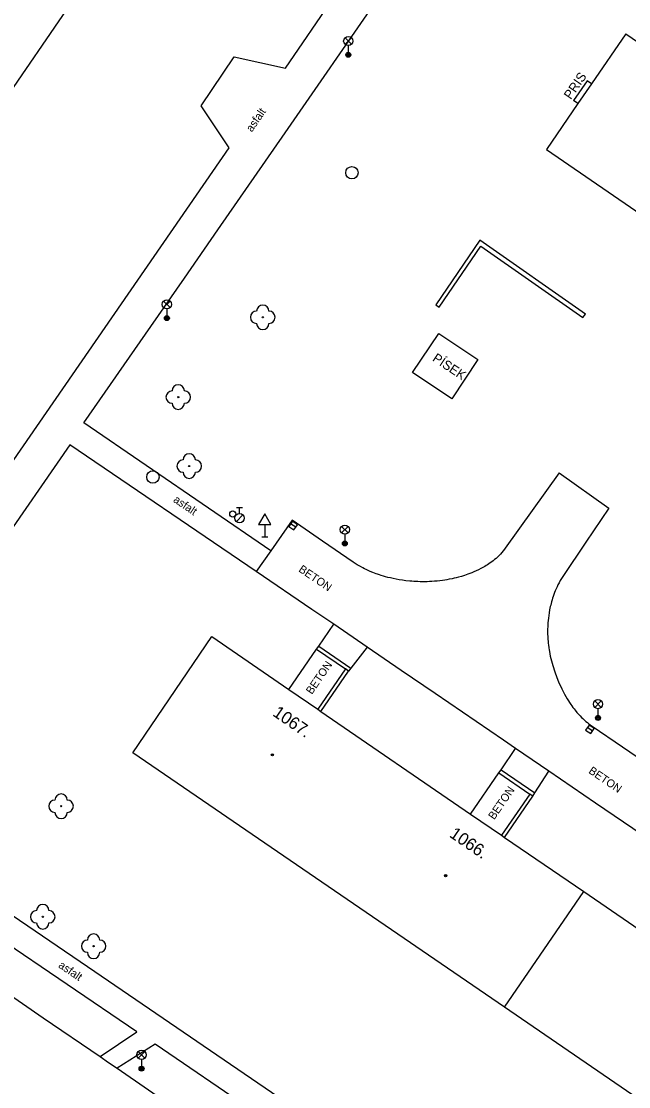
# Model space of a CAD drawing. Extents: x -539515 to -538098, y -1182060 to -1180157.
# Drawn here: x -538801 to -538751.7, y -1181426.9 to -1181340.3 of the extents above; entities that cross this region are included whole.
import ezdxf

# ---------------------------------------------------------------- set-up
doc = ezdxf.new("R2010")
doc.units = 0
for name, color, linetype in [('Vrstva 10', 7, 'Continuous'), ('Vrstva 11', 7, 'Continuous'), ('Vrstva 22', 7, 'Continuous'), ('Vrstva 24', 7, 'Continuous'), ('Vrstva 27', 7, 'Continuous'), ('Vrstva 28', 7, 'Continuous'), ('Vrstva 33', 7, 'Continuous'), ('Vrstva 34', 7, 'Continuous'), ('Vrstva 39', 7, 'Continuous'), ('Vrstva 40', 7, 'Continuous'), ('Vrstva 41', 7, 'Continuous'), ('Vrstva 47', 7, 'Continuous'), ('Vrstva 5', 7, 'Continuous'), ('Vrstva 7', 7, 'Continuous')]:
    doc.layers.add(name, color=color, linetype=linetype)

msp = doc.modelspace()

# ---------------------------------------------------------------- linework, layer by layer
at = {"layer": 'Vrstva 10'}
for p, q in [((-538769.24, -1181368.85), (-538767.12, -1181365.67)), ((-538767.12, -1181365.67), (-538763.94, -1181367.79)), ((-538763.94, -1181367.79), (-538766.06, -1181370.97)), ((-538766.06, -1181370.97), (-538769.24, -1181368.85)), ((-538757.34, -1181376.98), (-538753.31, -1181379.85)), ((-538777.44, -1181388.08), (-538781.95, -1181385.01)), ((-538761.875, -1181398.709), (-538767.4, -1181394.926)), ((-538754.816, -1181397.466), (-538754.67, -1181397.57)), ((-538754.67, -1181397.57), (-538744.795, -1181404.321)), ((-538803.861, -1181418.09), (-538799.239, -1181421.248)), ((-538799.239, -1181421.248), (-538794.62, -1181424.41))]:
    msp.add_line(p, q, dxfattribs=at)
for points in [[(-538757.34, -1181376.98), (-538759.53, -1181380.05), (-538761.72, -1181383.12), (-538761.775, -1181383.195), (-538761.887, -1181383.339), (-538762.002, -1181383.474), (-538762.118, -1181383.602), (-538762.236, -1181383.721), (-538762.353, -1181383.833), (-538762.471, -1181383.939), (-538762.589, -1181384.038), (-538762.706, -1181384.131), (-538762.822, -1181384.219), (-538762.937, -1181384.302), (-538763.05, -1181384.38), (-538763.162, -1181384.453), (-538763.271, -1181384.522), (-538763.379, -1181384.587), (-538763.485, -1181384.648)], [(-538753.31, -1181379.85), (-538755.175, -1181382.625), (-538757.04, -1181385.4), (-538757.152, -1181385.572), (-538757.254, -1181385.744), (-538757.349, -1181385.913), (-538757.437, -1181386.081), (-538757.517, -1181386.246), (-538757.591, -1181386.409), (-538757.659, -1181386.568), (-538757.721, -1181386.725), (-538757.778, -1181386.879), (-538757.83, -1181387.029), (-538757.878, -1181387.176), (-538757.922, -1181387.32), (-538757.962, -1181387.46), (-538757.998, -1181387.597), (-538758.031, -1181387.73), (-538758.062, -1181387.86), (-538758.114, -1181388.113), (-538758.157, -1181388.351)], [(-538779.02, -1181380.84), (-538780.762, -1181383.32), (-538781.95, -1181385.01)], [(-538773.282, -1181384.718), (-538773.488, -1181384.607), (-538773.64, -1181384.52), (-538773.752, -1181384.453), (-538773.918, -1181384.349), (-538774.08, -1181384.24), (-538776.55, -1181382.54), (-538779.02, -1181380.84)], [(-538763.485, -1181384.648), (-538763.694, -1181384.762), (-538763.894, -1181384.863), (-538764.084, -1181384.952), (-538764.264, -1181385.032), (-538764.435, -1181385.104), (-538764.597, -1181385.167), (-538764.749, -1181385.224), (-538764.893, -1181385.274), (-538765.028, -1181385.32), (-538765.282, -1181385.399), (-538765.506, -1181385.463), (-538765.701, -1181385.514), (-538765.871, -1181385.555), (-538766.02, -1181385.589), (-538766.28, -1181385.642), (-538766.472, -1181385.678), (-538766.616, -1181385.702), (-538766.829, -1181385.733), (-538767.04, -1181385.76), (-538767.255, -1181385.783), (-538767.467, -1181385.801), (-538767.673, -1181385.815), (-538767.876, -1181385.825), (-538768.073, -1181385.832), (-538768.266, -1181385.835), (-538768.453, -1181385.835), (-538768.636, -1181385.832), (-538768.814, -1181385.826), (-538768.987, -1181385.819), (-538769.155, -1181385.809), (-538769.318, -1181385.797), (-538769.476, -1181385.783), (-538769.783, -1181385.751), (-538770.07, -1181385.713), (-538770.34, -1181385.671), (-538770.591, -1181385.626), (-538770.827, -1181385.579), (-538771.046, -1181385.53), (-538771.251, -1181385.48), (-538771.442, -1181385.43), (-538771.619, -1181385.379), (-538771.785, -1181385.329), (-538771.939, -1181385.28), (-538772.083, -1181385.231), (-538772.217, -1181385.184), (-538772.465, -1181385.09), (-538772.679, -1181385.002), (-538772.864, -1181384.921), (-538773.024, -1181384.847), (-538773.162, -1181384.779), (-538773.282, -1181384.718)], [(-538772.93, -1181391.15), (-538775.653, -1181389.296), (-538777.44, -1181388.08)], [(-538758.157, -1181388.351), (-538758.191, -1181388.576), (-538758.218, -1181388.788), (-538758.239, -1181388.986), (-538758.255, -1181389.173), (-538758.267, -1181389.347), (-538758.275, -1181389.511), (-538758.279, -1181389.665), (-538758.282, -1181389.808), (-538758.28, -1181390.076), (-538758.272, -1181390.309), (-538758.261, -1181390.512), (-538758.247, -1181390.689), (-538758.233, -1181390.842), (-538758.218, -1181390.975), (-538758.187, -1181391.206), (-538758.16, -1181391.378), (-538758.138, -1181391.505), (-538758.101, -1181391.694), (-538758.06, -1181391.88), (-538758.013, -1181392.076), (-538757.964, -1181392.267), (-538757.913, -1181392.453), (-538757.861, -1181392.634), (-538757.808, -1181392.81), (-538757.753, -1181392.981), (-538757.698, -1181393.147), (-538757.642, -1181393.307), (-538757.586, -1181393.463), (-538757.529, -1181393.613), (-538757.472, -1181393.758), (-538757.356, -1181394.038), (-538757.24, -1181394.299), (-538757.126, -1181394.541), (-538757.013, -1181394.765), (-538756.903, -1181394.973), (-538756.795, -1181395.166), (-538756.69, -1181395.343), (-538756.589, -1181395.508), (-538756.49, -1181395.66), (-538756.396, -1181395.8), (-538756.305, -1181395.929), (-538756.218, -1181396.049), (-538756.134, -1181396.159), (-538756.054, -1181396.261), (-538755.9, -1181396.448), (-538755.761, -1181396.606), (-538755.636, -1181396.741), (-538755.524, -1181396.856), (-538755.424, -1181396.954), (-538755.335, -1181397.038), (-538755.175, -1181397.181), (-538755.053, -1181397.283), (-538754.959, -1181397.358), (-538754.816, -1181397.466)], [(-538767.4, -1181394.926), (-538770.164, -1181393.036), (-538772.93, -1181391.15)], [(-538758.19, -1181401.23), (-538760.881, -1181399.388), (-538761.875, -1181398.709)], [(-538750.603, -1181406.405), (-538754.398, -1181403.819), (-538758.19, -1181401.23)], [(-538794.62, -1181424.41), (-538793.935, -1181424.88), (-538793.25, -1181425.35), (-538790.692, -1181427.114), (-538786.861, -1181429.767)]]:
    msp.add_lwpolyline(points, dxfattribs=at)
at = {"layer": 'Vrstva 11'}
for p, q in [((-538779.58, -1181344.11), (-538765.75, -1181323.99)), ((-538779.601, -1181349.363), (-538771.42, -1181337.527)), ((-538786.42, -1181347.18), (-538783.75, -1181343.19)), ((-538783.75, -1181343.19), (-538779.58, -1181344.11)), ((-538784.14, -1181350.6), (-538786.42, -1181347.18)), ((-538785.06, -1181357.25), (-538779.601, -1181349.363)), ((-538819.07, -1181401.16), (-538784.14, -1181350.6)), ((-538795.95, -1181372.94), (-538790.503, -1181365.096)), ((-538780.762, -1181383.32), (-538795.95, -1181372.94)), ((-538797.09, -1181374.73), (-538816.55, -1181402.85)), ((-538781.95, -1181385.01), (-538797.09, -1181374.73)), ((-538777.038, -1181391.315), (-538774.697, -1181392.92)), ((-538776.868, -1181391.067), (-538774.264, -1181392.852)), ((-538762.061, -1181401.108), (-538759.309, -1181402.995)), ((-538762.231, -1181401.356), (-538759.717, -1181403.08)), ((-538816.55, -1181402.85), (-538795.05, -1181417.505)), ((-538791.63, -1181422.39), (-538817.84, -1181404.65)), ((-538795.05, -1181417.505), (-538773.55, -1181432.16)), ((-538794.62, -1181424.41), (-538791.63, -1181422.39)), ((-538790.14, -1181423.41), (-538793.25, -1181425.35)), ((-538761.68, -1181442.8), (-538790.14, -1181423.41))]:
    msp.add_line(p, q, dxfattribs=at)
for points in [[(-538790.503, -1181365.096), (-538787.78, -1181361.174), (-538785.06, -1181357.25)], [(-538779.286, -1181394.593), (-538777.038, -1181391.315), (-538776.868, -1181391.067), (-538775.653, -1181389.296)], [(-538772.93, -1181391.15), (-538774.264, -1181392.852), (-538774.45, -1181393.09)], [(-538764.533, -1181404.712), (-538762.231, -1181401.356), (-538762.061, -1181401.108), (-538760.881, -1181399.388)], [(-538759.47, -1181403.25), (-538759.309, -1181402.995), (-538758.19, -1181401.23)]]:
    msp.add_lwpolyline(points, dxfattribs=at)
at = {"layer": 'Vrstva 22'}
for centre in [(-538781.41, -1181364.36), (-538788.28, -1181370.84), (-538787.39, -1181376.44), (-538797.79, -1181404.07), (-538799.28, -1181413.05), (-538795.15, -1181415.44)]:
    msp.add_circle(centre, 0.05, dxfattribs=at)
for centre, start, end in [((-538781.91, -1181364.36), 90, 270), ((-538781.41, -1181363.86), 0, 180), ((-538780.91, -1181364.36), 270, 90), ((-538781.41, -1181364.86), 180, 0), ((-538788.28, -1181370.34), 0, 180), ((-538788.78, -1181370.84), 90, 270), ((-538787.78, -1181370.84), 270, 90), ((-538788.28, -1181371.34), 180, 0), ((-538787.89, -1181376.44), 90, 270), ((-538787.39, -1181375.94), 0, 180), ((-538786.89, -1181376.44), 270, 90), ((-538787.39, -1181376.94), 180, 0), ((-538798.29, -1181404.07), 90, 270), ((-538797.79, -1181403.57), 0, 180), ((-538797.29, -1181404.07), 270, 90), ((-538797.79, -1181404.57), 180, 0), ((-538799.28, -1181412.55), 0, 180), ((-538799.78, -1181413.05), 90, 270), ((-538798.78, -1181413.05), 270, 90), ((-538799.28, -1181413.55), 180, 0), ((-538795.65, -1181415.44), 90, 270), ((-538795.15, -1181414.94), 0, 180), ((-538794.65, -1181415.44), 270, 90), ((-538795.15, -1181415.94), 180, 0)]:
    msp.add_arc(centre, 0.5, start, end, dxfattribs=at)
at = {"layer": 'Vrstva 24'}
for p, q in [((-538755.075, -1181345.137), (-538756.18, -1181346.75)), ((-538754.719, -1181345.381), (-538755.075, -1181345.137)), ((-538755.823, -1181346.994), (-538756.18, -1181346.75))]:
    msp.add_line(p, q, dxfattribs=at)
at = {"layer": 'Vrstva 27'}
for p, q in [((-538778.738, -1181381.416), (-538779.15, -1181381.134)), ((-538754.636, -1181397.964), (-538755.048, -1181397.682))]:
    msp.add_line(p, q, dxfattribs=at)
for points in [[(-538778.596, -1181381.21), (-538779.009, -1181380.927), (-538779.292, -1181381.34), (-538778.879, -1181381.623)], [(-538754.494, -1181397.758), (-538754.907, -1181397.475), (-538755.19, -1181397.888), (-538754.777, -1181398.171)]]:
    msp.add_lwpolyline(points, close=True, dxfattribs=at)
for centre in [(-538774.17, -1181352.61), (-538790.34, -1181377.33)]:
    msp.add_circle(centre, 0.5, dxfattribs=at)
at = {"layer": 'Vrstva 28'}
for p, q in [((-538783.558, -1181380.942), (-538783.028, -1181380.412)), ((-538783.55, -1181379.795), (-538783.05, -1181379.795)), ((-538783.3, -1181380.295), (-538783.3, -1181379.795))]:
    msp.add_line(p, q, dxfattribs=at)
for centre, radius in [((-538783.85, -1181380.34), 0.25), ((-538783.3, -1181380.67), 0.375)]:
    msp.add_circle(centre, radius, dxfattribs=at)
at = {"layer": 'Vrstva 33'}
for p, q in [((-538774.735, -1181342.18), (-538774.205, -1181341.65)), ((-538774.735, -1181341.65), (-538774.205, -1181342.18)), ((-538774.47, -1181342.29), (-538774.47, -1181343.04)), ((-538789.465, -1181363.57), (-538788.935, -1181363.04)), ((-538789.465, -1181363.04), (-538788.935, -1181363.57)), ((-538789.2, -1181363.68), (-538789.2, -1181364.43)), ((-538775.015, -1181381.87), (-538774.485, -1181381.34)), ((-538775.015, -1181381.34), (-538774.485, -1181381.87)), ((-538774.75, -1181381.98), (-538774.75, -1181382.73)), ((-538754.455, -1181396.04), (-538753.925, -1181395.51)), ((-538754.455, -1181395.51), (-538753.925, -1181396.04)), ((-538754.19, -1181396.15), (-538754.19, -1181396.9)), ((-538791.525, -1181424.53), (-538790.995, -1181424)), ((-538791.525, -1181424), (-538790.995, -1181424.53)), ((-538791.26, -1181424.64), (-538791.26, -1181425.39))]:
    msp.add_line(p, q, dxfattribs=at)
for centre, radius in [((-538774.47, -1181341.915), 0.375), ((-538774.47, -1181343.04), 0.2), ((-538774.47, -1181343.04), 0.145), ((-538774.47, -1181343.04), 0.0876), ((-538789.2, -1181363.305), 0.375), ((-538789.2, -1181364.43), 0.2), ((-538789.2, -1181364.43), 0.145), ((-538789.2, -1181364.43), 0.0876), ((-538774.75, -1181381.605), 0.375), ((-538774.75, -1181382.73), 0.2), ((-538774.75, -1181382.73), 0.145), ((-538774.75, -1181382.73), 0.0876), ((-538754.19, -1181395.775), 0.375), ((-538754.19, -1181396.9), 0.2), ((-538754.19, -1181396.9), 0.145), ((-538754.19, -1181396.9), 0.0876), ((-538791.26, -1181424.265), 0.375), ((-538791.26, -1181425.39), 0.2), ((-538791.26, -1181425.39), 0.145), ((-538791.26, -1181425.39), 0.0876)]:
    msp.add_circle(centre, radius, dxfattribs=at)
at = {"layer": 'Vrstva 34'}
for p, q in [((-538781.251, -1181381.18), (-538781.251, -1181382.198)), ((-538781.501, -1181382.198), (-538781.001, -1181382.198))]:
    msp.add_line(p, q, dxfattribs=at)
msp.add_lwpolyline([(-538781.751, -1181381.18), (-538780.751, -1181381.18), (-538781.251, -1181380.314)], close=True, dxfattribs=at)
at = {"layer": 'Vrstva 39'}
for centre, radius in [((-538780.635, -1181399.896), 0.09), ((-538780.635, -1181399.896), 0.0398), ((-538766.568, -1181409.705), 0.09), ((-538766.568, -1181409.705), 0.0398)]:
    msp.add_circle(centre, radius, dxfattribs=at)
at = {"layer": 'Vrstva 5'}
for p, q in [((-538829.45, -1181386.2), (-538788.38, -1181326.32)), ((-538758.38, -1181350.73), (-538683.63, -1181402.09)), ((-538791.96, -1181399.73), (-538785.56, -1181390.29)), ((-538761.787, -1181420.406), (-538755.349, -1181411.011))]:
    msp.add_line(p, q, dxfattribs=at)
for points in [[(-538751.94, -1181341.32), (-538754.719, -1181345.381), (-538755.823, -1181346.994), (-538758.38, -1181350.73)], [(-538751.94, -1181341.32), (-538745.831, -1181345.515)], [(-538785.56, -1181390.29), (-538779.286, -1181394.593)], [(-538779.286, -1181394.593), (-538776.945, -1181396.198)], [(-538776.945, -1181396.198), (-538776.698, -1181396.368)], [(-538776.698, -1181396.368), (-538764.533, -1181404.712)], [(-538761.787, -1181420.406), (-538791.96, -1181399.73)], [(-538764.533, -1181404.712), (-538762.019, -1181406.436)], [(-538762.019, -1181406.436), (-538761.772, -1181406.606)], [(-538761.772, -1181406.606), (-538755.349, -1181411.011)], [(-538755.349, -1181411.011), (-538749.475, -1181415.04)], [(-538731.98, -1181440.83), (-538761.787, -1181420.406)]]:
    msp.add_lwpolyline(points, dxfattribs=at)
at = {"layer": 'Vrstva 7'}
for p, q in [((-538767.081, -1181363.537), (-538763.7, -1181358.58)), ((-538763.7, -1181358.58), (-538755.411, -1181364.377)), ((-538774.697, -1181392.92), (-538776.945, -1181396.198)), ((-538759.717, -1181403.08), (-538762.019, -1181406.436))]:
    msp.add_line(p, q, dxfattribs=at)
for points in [[(-538763.79, -1181358.09), (-538767.37, -1181363.34), (-538767.081, -1181363.537)], [(-538755.411, -1181364.377), (-538755.21, -1181364.09), (-538763.79, -1181358.09)], [(-538776.698, -1181396.368), (-538774.45, -1181393.09), (-538774.697, -1181392.92)], [(-538761.772, -1181406.606), (-538759.47, -1181403.25), (-538759.717, -1181403.08)]]:
    msp.add_lwpolyline(points, dxfattribs=at)

# ---------------------------------------------------------------- texts
at = {"layer": 'Vrstva 40'}
for s, rotation, p in [('asfalt', 55.32945, (-538782.303, -1181349.356)), ('asfalt', 325.82365, (-538788.741, -1181379.308)), ('BETON', 325.75651, (-538778.559, -1181384.966)), ('BETON', 55.55573, (-538777.427, -1181395.038)), ('BETON', 325.69991, (-538755.008, -1181401.335)), ('BETON', 55.55573, (-538762.618, -1181405.217)), ('asfalt', 325.90825, (-538798.069, -1181417.124))]:
    msp.add_text(s, height=0.65, rotation=rotation, dxfattribs=at).set_placement(p)
at = {"layer": 'Vrstva 41'}
for s, rotation, p in [('PRIS', 55.58656, (-538756.401, -1181346.718)), ('PÍSEK', 326.30993, (-538767.693, -1181367.85))]:
    msp.add_text(s, height=0.75, rotation=rotation, dxfattribs=at).set_placement(p)
at = {"layer": 'Vrstva 47'}
for s, p in [('1067.', (-538780.68, -1181396.668)), ('1066.', (-538766.325, -1181406.513))]:
    msp.add_text(s, height=1, rotation=325.55433, dxfattribs=at).set_placement(p)

doc.saveas('drawing.dxf')
